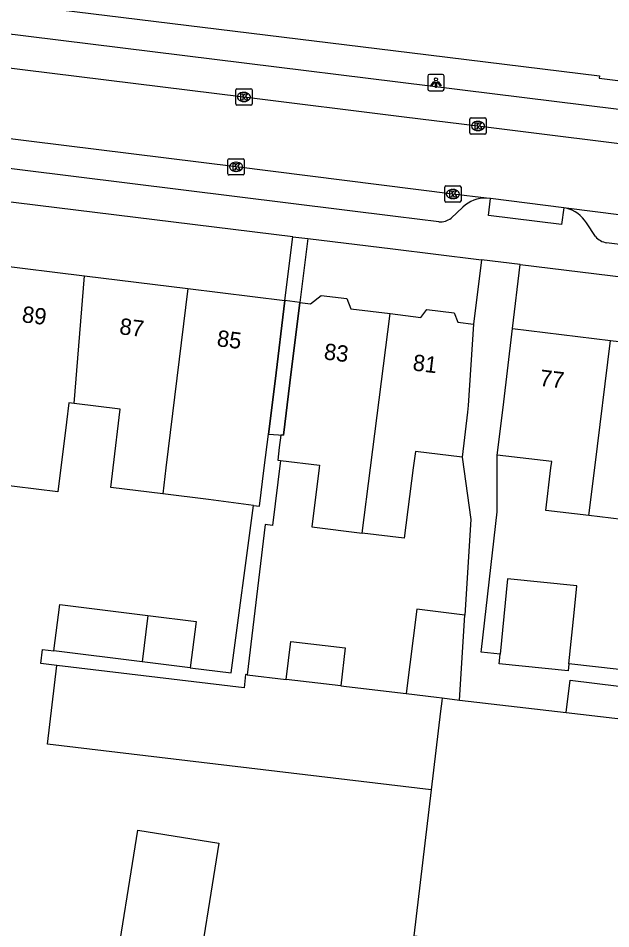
# Model space of a CAD drawing. Extents: x 158087 to 159494, y 382905 to 383981.
# Drawn here: x 158322.6 to 158358.9, y 383221.8 to 383277.6 of the extents above; entities that cross this region are included whole.
import ezdxf

# ---------------------------------------------------------------- set-up
doc = ezdxf.new("R2010")
doc.units = 0
for name, color, linetype in [('IMGEO_Kolk', 7, 'Continuous'), ('IMGEO_Lichtpunt', 7, 'Continuous'), ('IMGEO_Pand', 7, 'Continuous'), ('IMGEO_Pand_nummerreeks', 7, 'Continuous'), ('IMGEO_Pand_overbouw', 7, 'Continuous'), ('IMGEO_Rijbaan_lokaal_open', 7, 'Continuous'), ('IMGEO_Voetpad_open', 7, 'Continuous')]:
    doc.layers.add(name, color=color, linetype=linetype)

msp = doc.modelspace()

# ---------------------------------------------------------------- linework, layer by layer
at = {"layer": 'IMGEO_Kolk'}
for p, q in [((158335.899, 383272.301), (158335.899, 383273.153)), ((158335.974, 383273.227), (158336.826, 383273.227)), ((158336.387, 383273.007), (158336.412, 383273.007)), ((158336.9, 383273.153), (158336.9, 383272.301)), ((158336.41, 383272.447), (158336.385, 383272.447)), ((158336.826, 383272.227), (158335.974, 383272.227)), ((158350.243, 383270.523), (158350.243, 383271.375)), ((158350.318, 383271.449), (158351.17, 383271.449)), ((158350.731, 383271.229), (158350.756, 383271.229)), ((158351.244, 383271.375), (158351.244, 383270.523)), ((158350.754, 383270.669), (158350.729, 383270.669)), ((158351.17, 383270.449), (158350.318, 383270.449)), ((158335.418, 383268.018), (158335.418, 383268.87)), ((158335.493, 383268.944), (158336.345, 383268.944)), ((158335.906, 383268.724), (158335.931, 383268.724)), ((158336.419, 383268.87), (158336.419, 383268.018)), ((158336.345, 383267.944), (158335.493, 383267.944)), ((158335.929, 383268.164), (158335.904, 383268.164)), ((158348.7, 383266.351), (158348.7, 383267.203)), ((158348.775, 383267.277), (158349.627, 383267.277)), ((158349.188, 383267.057), (158349.213, 383267.057)), ((158349.701, 383267.203), (158349.701, 383266.351)), ((158349.627, 383266.277), (158348.775, 383266.277)), ((158349.211, 383266.497), (158349.186, 383266.497))]:
    msp.add_line(p, q, dxfattribs=at)
for points in [[(158335.899, 383272.301), (158335.899, 383273.153)], [(158335.974, 383273.227), (158336.826, 383273.227)], [(158336.22, 383272.927), (158336.343, 383272.927), (158336.343, 383272.776), (158336.473, 383272.927), (158336.637, 383272.927), (158336.491, 383272.776), (158336.644, 383272.527), (158336.492, 383272.527), (158336.407, 383272.691), (158336.343, 383272.624), (158336.343, 383272.527), (158336.22, 383272.527), (158336.22, 383272.927)], [(158336.9, 383273.153), (158336.9, 383272.301)], [(158336.826, 383272.227), (158335.974, 383272.227)], [(158350.243, 383270.523), (158350.243, 383271.375)], [(158350.318, 383271.449), (158351.17, 383271.449)], [(158351.244, 383271.375), (158351.244, 383270.523)], [(158350.564, 383271.149), (158350.687, 383271.149), (158350.687, 383270.998), (158350.817, 383271.149), (158350.981, 383271.149), (158350.835, 383270.998), (158350.988, 383270.749), (158350.836, 383270.749), (158350.751, 383270.913), (158350.687, 383270.846), (158350.687, 383270.749), (158350.564, 383270.749), (158350.564, 383271.149)], [(158351.17, 383270.449), (158350.318, 383270.449)], [(158335.418, 383268.018), (158335.418, 383268.87)], [(158335.493, 383268.944), (158336.345, 383268.944)], [(158335.739, 383268.644), (158335.862, 383268.644), (158335.862, 383268.493), (158335.992, 383268.644), (158336.156, 383268.644), (158336.01, 383268.493), (158336.163, 383268.244), (158336.011, 383268.244), (158335.926, 383268.408), (158335.862, 383268.341), (158335.862, 383268.244), (158335.739, 383268.244), (158335.739, 383268.644)], [(158336.419, 383268.87), (158336.419, 383268.018)], [(158336.345, 383267.944), (158335.493, 383267.944)], [(158348.7, 383266.351), (158348.7, 383267.203)], [(158348.775, 383267.277), (158349.627, 383267.277)], [(158349.021, 383266.977), (158349.144, 383266.977), (158349.144, 383266.826), (158349.274, 383266.977), (158349.438, 383266.977), (158349.292, 383266.826), (158349.445, 383266.577), (158349.293, 383266.577), (158349.208, 383266.741), (158349.144, 383266.674), (158349.144, 383266.577), (158349.021, 383266.577), (158349.021, 383266.977)], [(158349.701, 383267.203), (158349.701, 383266.351)], [(158349.627, 383266.277), (158348.775, 383266.277)]]:
    msp.add_lwpolyline(points, dxfattribs=at)
for centre, start, end in [((158335.976, 383273.151), 91.552, 178.448), ((158335.976, 383273.151), 91.552, 178.448), ((158336.824, 383273.151), 1.552, 88.448), ((158336.824, 383273.151), 1.552, 88.448), ((158335.976, 383272.303), 181.552, 268.448), ((158335.976, 383272.303), 181.552, 268.448), ((158336.824, 383272.303), 271.552, 358.448), ((158336.824, 383272.303), 271.552, 358.448), ((158350.32, 383271.373), 91.552, 178.448), ((158350.32, 383271.373), 91.552, 178.448), ((158351.168, 383271.373), 1.552, 88.448), ((158351.168, 383271.373), 1.552, 88.448), ((158350.32, 383270.525), 181.552, 268.448), ((158350.32, 383270.525), 181.552, 268.448), ((158351.168, 383270.525), 271.552, 358.448), ((158351.168, 383270.525), 271.552, 358.448), ((158335.495, 383268.868), 91.552, 178.448), ((158335.495, 383268.868), 91.552, 178.448), ((158336.343, 383268.868), 1.552, 88.448), ((158336.343, 383268.868), 1.552, 88.448), ((158335.495, 383268.02), 181.552, 268.448), ((158335.495, 383268.02), 181.552, 268.448), ((158336.343, 383268.02), 271.552, 358.448), ((158336.343, 383268.02), 271.552, 358.448), ((158348.777, 383267.201), 91.552, 178.448), ((158348.777, 383267.201), 91.552, 178.448), ((158349.625, 383267.201), 1.552, 88.448), ((158349.625, 383267.201), 1.552, 88.448), ((158348.777, 383266.353), 181.552, 268.448), ((158348.777, 383266.353), 181.552, 268.448), ((158349.625, 383266.353), 271.552, 358.448), ((158349.625, 383266.353), 271.552, 358.448)]:
    msp.add_arc(centre, 0.0765, start, end, dxfattribs=at)
for centre, major_axis, ratio, start_param, end_param in [((158336.386, 383272.727), (-0.387, 0.002), 0.722429, 4.712389, 7.853982), ((158336.411, 383272.727), (-0.39, 0.002), 0.717154, 1.570796, 4.712389), ((158350.73, 383270.949), (-0.387, 0.002), 0.722429, 4.712389, 7.853982), ((158350.755, 383270.949), (-0.39, 0.002), 0.717154, 1.570796, 4.712389), ((158335.905, 383268.444), (-0.387, 0.002), 0.722429, 4.712389, 7.853982), ((158335.93, 383268.444), (-0.39, 0.002), 0.717154, 1.570796, 4.712389), ((158349.187, 383266.777), (-0.387, 0.002), 0.722429, 4.712389, 7.853982), ((158349.212, 383266.777), (-0.39, 0.002), 0.717154, 1.570796, 4.712389)]:
    msp.add_ellipse(centre, major_axis=major_axis, ratio=ratio, start_param=start_param, end_param=end_param, dxfattribs=at)
at = {"layer": 'IMGEO_Lichtpunt'}
for p, q in [((158347.669, 383274.008), (158347.669, 383273.201)), ((158347.669, 383274.008), (158347.669, 383273.201)), ((158348.571, 383274.103), (158347.763, 383274.103)), ((158348.571, 383274.103), (158347.763, 383274.103)), ((158348.665, 383273.201), (158348.665, 383274.008)), ((158348.665, 383273.201), (158348.665, 383274.008)), ((158347.763, 383273.107), (158348.571, 383273.107)), ((158347.763, 383273.107), (158348.571, 383273.107))]:
    msp.add_line(p, q, dxfattribs=at)
for points in [[(158348.043, 383273.672), (158348.082, 383273.644), (158347.894, 383273.382), (158347.856, 383273.409), (158348.043, 383273.672)], [(158348.145, 383273.624), (158348.192, 383273.624), (158348.192, 383273.302), (158348.145, 383273.302), (158348.145, 383273.624)], [(158348.255, 383273.644), (158348.293, 383273.671), (158348.48, 383273.409), (158348.441, 383273.381), (158348.255, 383273.644)]]:
    msp.add_lwpolyline(points, dxfattribs=at)
msp.add_circle((158348.168, 383273.806), 0.0994, dxfattribs=at)
for centre, start, end in [((158347.763, 383274.008), 90, 180), ((158347.763, 383274.008), 90, 180), ((158348.571, 383274.008), 0, 90), ((158348.571, 383274.008), 0, 90), ((158347.763, 383273.201), 180, 270), ((158347.763, 383273.201), 180, 270), ((158348.571, 383273.201), 270, 0), ((158348.571, 383273.201), 270, 360)]:
    msp.add_arc(centre, 0.0946, start, end, dxfattribs=at)
at = {"layer": 'IMGEO_Pand'}
for points in [[(158320.994, 383262.451), (158326.628, 383261.758)], [(158325.991, 383253.948), (158326.628, 383261.758)], [(158326.628, 383261.758), (158332.959, 383260.98)], [(158332.959, 383260.98), (158331.617, 383250), (158331.423, 383248.409)], [(158332.959, 383260.98), (158338.914, 383260.247)], [(158336.996, 383247.692), (158337.359, 383247.643), (158337.65, 383250), (158337.904, 383252.061), (158338.305, 383255.313), (158338.914, 383260.247)], [(158339.827, 383260.134), (158339.219, 383255.203), (158338.823, 383251.999), (158338.662, 383252.01), (158338.567, 383251.242), (158338.472, 383250.474), (158338.632, 383250.454)], [(158339.827, 383260.134), (158340.489, 383260.052), (158341.14, 383260.56), (158342.696, 383260.368), (158342.96, 383259.744), (158345.35, 383259.449)], [(158345.35, 383259.449), (158347.232, 383259.217), (158347.6, 383259.705), (158349.276, 383259.498), (158349.516, 383258.931), (158350.475, 383258.813)], [(158343.641, 383246.002), (158344.149, 383250), (158345.35, 383259.449)], [(158350.475, 383258.813), (158350.131, 383253.825), (158350.107, 383253.403), (158349.768, 383250.653)], [(158351.924, 383250.782), (158352.285, 383253.696), (158352.853, 383258.535)], [(158352.853, 383258.535), (158358.859, 383257.811)], [(158357.537, 383247.08), (158357.897, 383250), (158358.859, 383257.811)], [(158358.859, 383257.811), (158364.919, 383257.081)], [(158325.991, 383253.948), (158325.68, 383253.986), (158325.533, 383252.794), (158325.008, 383248.534), (158319.658, 383249.194), (158320.183, 383253.454)], [(158331.423, 383248.409), (158328.253, 383248.801), (158328.394, 383250), (158328.816, 383253.6), (158325.991, 383253.948)], [(158349.768, 383250.653), (158346.907, 383251.006), (158346.776, 383250), (158346.215, 383245.684), (158343.641, 383246.002)], [(158357.537, 383247.08), (158354.899, 383247.397), (158355.212, 383250), (158355.257, 383250.381), (158351.924, 383250.782)], [(158338.632, 383250.454), (158341.04, 383250.158), (158341.02, 383250), (158340.565, 383246.382), (158343.641, 383246.002)], [(158363.964, 383249.335), (158363.596, 383246.352), (158357.537, 383247.08)], [(158336.996, 383247.692), (158334.235, 383248.061), (158331.423, 383248.409)], [(158356.315, 383237.985), (158356.632, 383241.117), (158356.8, 383242.769), (158352.559, 383243.199), (158352.092, 383238.586)], [(158324.76, 383238.784), (158325.111, 383241.627), (158330.515, 383240.959)], [(158349.942, 383240.972), (158346.999, 383241.347), (158346.34, 383236.165)], [(158330.515, 383240.959), (158330.168, 383238.115)], [(158330.515, 383240.959), (158333.464, 383240.594), (158333.112, 383237.751)], [(158349.616, 383235.775), (158349.942, 383240.972)], [(158338.998, 383237.04), (158339.266, 383239.353), (158342.606, 383238.966), (158342.336, 383236.642)], [(158330.168, 383238.115), (158324.76, 383238.784)], [(158356.315, 383237.985), (158356.272, 383237.566), (158352.032, 383237.995), (158352.092, 383238.586)], [(158347.878, 383230.272), (158324.358, 383233.075), (158324.932, 383237.892)], [(158336.601, 383237.325), (158336.503, 383237.337), (158336.406, 383236.525), (158324.932, 383237.892)], [(158333.112, 383237.751), (158330.168, 383238.115)], [(158336.601, 383237.325), (158338.998, 383237.04)], [(158342.336, 383236.642), (158338.998, 383237.04)], [(158342.336, 383236.642), (158346.34, 383236.165)], [(158356.147, 383235.013), (158356.387, 383236.981), (158362.343, 383236.256)], [(158346.34, 383236.165), (158348.2, 383235.943), (158348.549, 383235.903)], [(158348.549, 383235.903), (158348.524, 383235.697), (158348.452, 383235.089), (158347.878, 383230.272)], [(158348.549, 383235.903), (158349.616, 383235.775)], [(158349.616, 383235.775), (158356.147, 383235.013)], [(158356.147, 383235.013), (158362.11, 383234.317)], [(158347.878, 383230.272), (158346.812, 383221.322), (158348.025, 383221.211)], [(158334.867, 383227.001), (158333.367, 383217.696), (158328.404, 383218.496), (158329.904, 383227.801), (158334.867, 383227.001)]]:
    msp.add_lwpolyline(points, dxfattribs=at)
at = {"layer": 'IMGEO_Pand_overbouw'}
msp.add_lwpolyline([(158338.823, 383251.999), (158339.219, 383255.203), (158339.827, 383260.134), (158338.914, 383260.247), (158338.305, 383255.313), (158337.904, 383252.061)], close=True, dxfattribs=at)
at = {"layer": 'IMGEO_Rijbaan_lokaal_open'}
for points in [[(158316.441, 383275.218), (158319.512, 383274.807), (158336.396, 383272.726), (158346.217, 383271.509), (158350.74, 383270.948), (158362.686, 383269.472), (158365.523, 383269.112)], [(158351.265, 383266.527), (158349.197, 383266.778), (158335.915, 383268.445), (158318.913, 383270.55), (158317.051, 383270.783)], [(158351.504, 383266.498), (158351.265, 383266.527)], [(158355.992, 383265.939), (158351.504, 383266.498)], [(158356.136, 383265.91), (158355.992, 383265.939)], [(158366.328, 383264.605), (158361.155, 383265.283), (158356.136, 383265.91)]]:
    msp.add_lwpolyline(points, dxfattribs=at)
at = {"layer": 'IMGEO_Voetpad_open'}
for points in [[(158315.314, 383279.287), (158346.553, 383275.453), (158358.185, 383274.026), (158358.16, 383273.883), (158368.763, 383272.542)], [(158363.015, 383271.514), (158319.388, 383276.89)], [(158339.394, 383264.164), (158277.718, 383271.726)], [(158348.352, 383265.074), (158345.696, 383265.404), (158319.534, 383268.652)], [(158355.992, 383265.939), (158355.863, 383264.907), (158351.375, 383265.466), (158351.504, 383266.498)], [(158349.819, 383265.98), (158349.089, 383265.299)], [(158357.942, 383264.176), (158357.386, 383265.013)], [(158338.914, 383260.247), (158339.394, 383264.164)], [(158339.394, 383264.164), (158340.307, 383264.052)], [(158340.307, 383264.052), (158339.827, 383260.134)], [(158340.307, 383264.052), (158345.526, 383263.412), (158350.794, 383262.766), (158350.957, 383262.746)], [(158364.081, 383263.113), (158358.622, 383263.791)], [(158350.957, 383262.746), (158350.475, 383258.813)], [(158353.332, 383262.456), (158350.957, 383262.746)], [(158352.853, 383258.535), (158353.332, 383262.456)], [(158353.332, 383262.456), (158436.049, 383252.351), (158455.212, 383250), (158496.63, 383244.919)], [(158349.768, 383250.653), (158350.31, 383246.84), (158349.942, 383240.972)], [(158352.092, 383238.586), (158350.938, 383238.703), (158350.956, 383238.86), (158351.924, 383247.313), (158351.924, 383250.782)], [(158338.632, 383250.454), (158338.141, 383246.477), (158337.698, 383246.532), (158336.601, 383237.325)], [(158333.112, 383237.751), (158335.625, 383237.44), (158336.996, 383247.692)], [(158324.932, 383237.892), (158323.96, 383238.008), (158324.066, 383238.87), (158324.76, 383238.784)], [(158362.469, 383237.296), (158356.315, 383237.985)]]:
    msp.add_lwpolyline(points, dxfattribs=at)
for centre, radius, start, end in [((158351.219, 383264.463), 2.065, 88.7341, 132.7077), ((158355.668, 383263.938), 2.027, 32.0336, 76.64), ((158348.437, 383266.114), 1.044, 265.3175, 308.6365), ((158358.814, 383264.923), 1.148, 220.5862, 260.3788)]:
    msp.add_arc(centre, radius, start, end, dxfattribs=at)

# ---------------------------------------------------------------- texts
at = {"layer": 'IMGEO_Pand_nummerreeks'}
for s, rotation, p in [('89', 352.987, (158322.761, 383258.93)), ('87', 352.9875, (158328.733, 383258.195)), ('85', 352.987, (158334.707, 383257.46)), ('83', 352.9297, (158341.265, 383256.65)), ('81', 352.928, (158346.702, 383255.975)), ('77', 353.1297, (158354.479, 383255.035))]:
    msp.add_text(s, height=1, rotation=rotation, dxfattribs=at).set_placement(p)

doc.saveas('drawing.dxf')
